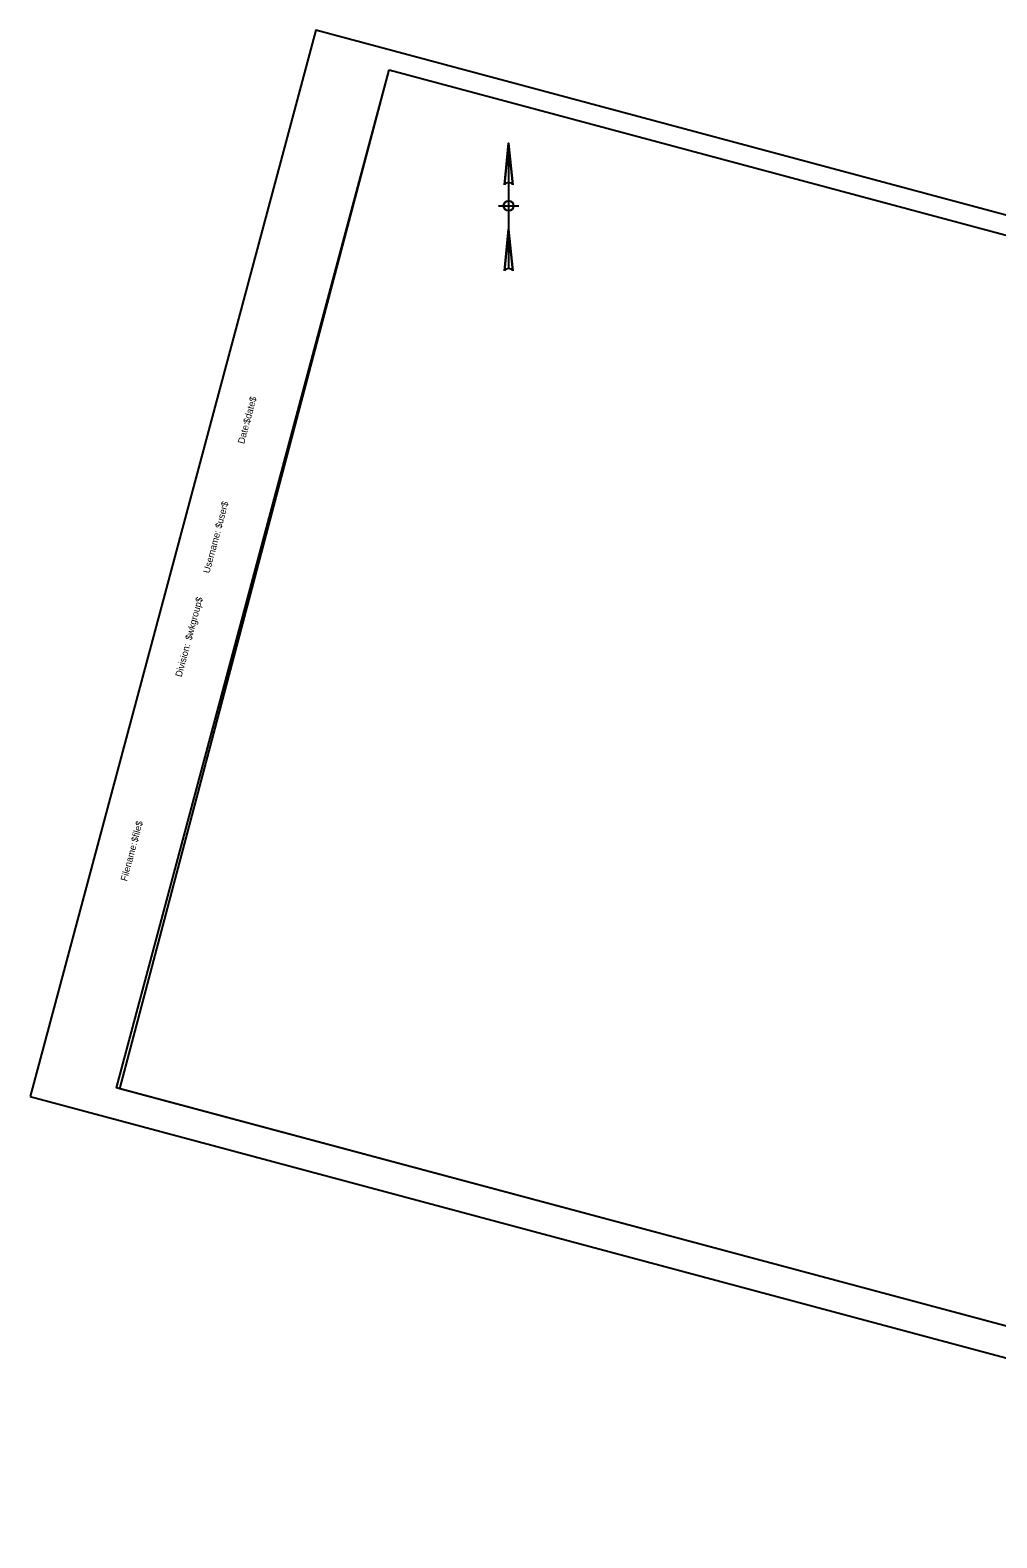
# Model space of a CAD drawing. Extents: x 1765825 to 1766788, y 479853 to 480605.
# Drawn here: x 1765825 to 1766307, y 479853 to 480605 of the extents above; entities that cross this region are included whole.
import ezdxf

# ---------------------------------------------------------------- set-up
doc = ezdxf.new("R2010")
doc.units = 0
for name, color, linetype in [('BORDER', 7, 'Continuous'), ('CLIPS', 7, 'Continuous'), ('H_V CONTROLS', 7, 'Continuous'), ('PLOT BOUNDARY', 7, 'Continuous')]:
    doc.layers.add(name, color=color, linetype=linetype)

msp = doc.modelspace()

# ---------------------------------------------------------------- linework, layer by layer
at = {"layer": 'BORDER'}
msp.add_lwpolyline([(1766003.93, 480584.67), (1766776.67, 480377.62), (1766640.79, 479870.5), (1765868.05, 480077.56)], close=True, dxfattribs=at)
at = {"layer": 'CLIPS'}
msp.add_lwpolyline([(1766003.93, 480584.67), (1766728.37, 480390.56), (1766592.49, 479883.45), (1765869.61, 480076.98)], close=True, dxfattribs=at)
at = {"layer": 'H_V CONTROLS'}
for p, q in [((1766061.35, 480527.38), (1766063.43, 480548.21)), ((1766063.43, 480548.21), (1766063.43, 480485.71)), ((1766063.43, 480548.21), (1766065.52, 480527.38)), ((1766058.43, 480516.96), (1766068.43, 480516.96)), ((1766061.35, 480484.59), (1766063.43, 480505.43)), ((1766063.43, 480505.43), (1766065.52, 480484.59))]:
    msp.add_line(p, q, dxfattribs=at)
for points in [[(1766065.52, 480527.38), (1766063.43, 480548.21), (1766062.39, 480537.8), (1766061.35, 480527.38)], [(1766065.52, 480484.59), (1766063.43, 480505.43), (1766062.39, 480495.01), (1766061.35, 480484.59)]]:
    msp.add_lwpolyline(points, dxfattribs=at)
msp.add_circle((1766063.43, 480516.96), 2.5, dxfattribs=at)
for centre in [(1766063.43, 480526), (1766063.43, 480526), (1766063.43, 480483.21), (1766063.43, 480483.21)]:
    msp.add_arc(centre, 2.5, 33.55731, 146.44269, dxfattribs=at)
at = {"layer": 'PLOT BOUNDARY'}
msp.add_lwpolyline([(1765825, 480073.26), (1766646.04, 479853.26), (1766788.39, 480384.52), (1765967.35, 480604.52)], close=True, dxfattribs=at)

# ---------------------------------------------------------------- texts
at = {"layer": 'BORDER'}
for s, p in [('$date$', (1765934.31, 480408.2)), ('Date:', (1765931.61, 480398.12)), ('$user$', (1765920.31, 480355.98)), ('Username:', (1765914.33, 480333.65)), ('$wkgroup$', (1765905.4, 480300.33)), ('Division:', (1765900.48, 480281.96)), ('$file$', (1765878.43, 480199.66)), ('Filename:', (1765873.22, 480180.21))]:
    msp.add_text(s, height=3.348, rotation=75, dxfattribs=at).set_placement(p)

doc.saveas('drawing.dxf')
